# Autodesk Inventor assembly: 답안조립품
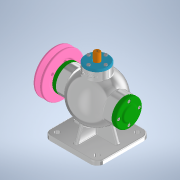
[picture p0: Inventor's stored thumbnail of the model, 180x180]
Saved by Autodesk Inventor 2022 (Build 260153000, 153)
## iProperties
Created: 2024-04
Part Number: 답안조립품
Document SubType Name: Assembly
Designer: user
Author: user
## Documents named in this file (16)
- C:\Users\user\Desktop\740406V1007\답안조립품.iam
- C:\Users\user\Desktop\740406V1007\본체.ipt
- C:\Users\user\Desktop\740406V1007\뒤커버.ipt
- C:\Users\user\Desktop\740406V1007\앞커버.ipt
- C:\Users\user\Desktop\740406V1007\상부커버.ipt
- C:\Users\user\Desktop\740406V1007\베어링- 6202.ipt
- KS B 2023 - 6202 - 15 x 35 x 11 - 7.8.ipt
- C:\Users\user\Desktop\740406V1007\칼라.ipt
- C:\Users\user\Desktop\740406V1007\편심축.ipt
- C:\Users\user\Desktop\740406V1007\키 4 x 4 x 12.ipt
- C:\Users\user\Desktop\740406V1007\오일실 15 30 7.ipt
- C:\Users\user\Desktop\740406V1007\V-벨트풀리.ipt
- C:\Users\user\Desktop\740406V1007\너트 M8.ipt
- C:\Users\user\Desktop\740406V1007\볼트 M4 x 16.ipt
- C:\Users\user\Desktop\740406V1007\볼트 M4 x 12.ipt
- C:\Users\user\Desktop\740406V1007\슬라이드.ipt
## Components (15 placed, 4 different names)
1. KS B 2023 - 6202 - 15 x 35 x 11 - 7.8:1
2. KS B 2023 - 6202 - 15 x 35 x 11 - 7.8:2
3. V-벨트풀리:1
4. ISO 4762 M4 x 16:1
5. ISO 4762 M4 x 16:2
6. ISO 4762 M4 x 16:3
7. ISO 4762 M4 x 16:4
8. ISO 4762 M4 x 16:5
9. ISO 4762 M4 x 16:6
10. ISO 4762 M4 x 16:7
11. ISO 4762 M4 x 16:8
12. KS B 1021 - 에 따름 ISO 1207 - 미터 A  M 4 x 12:1
13. KS B 1021 - 에 따름 ISO 1207 - 미터 A  M 4 x 12:2
14. KS B 1021 - 에 따름 ISO 1207 - 미터 A  M 4 x 12:3
15. KS B 1021 - 에 따름 ISO 1207 - 미터 A  M 4 x 12:4
